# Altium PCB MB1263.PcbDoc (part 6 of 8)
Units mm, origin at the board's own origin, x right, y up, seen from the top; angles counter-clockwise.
Board outline 86 x 120 mm, 6 copper layers (Top Layer, Signal Layer 1, Signal Layer 2, Signal Layer 3, Signal Layer 4, Bottom Layer), stack 1.556 mm thick; 392 components, 421 nets, 1978 pads, 1444 vias.
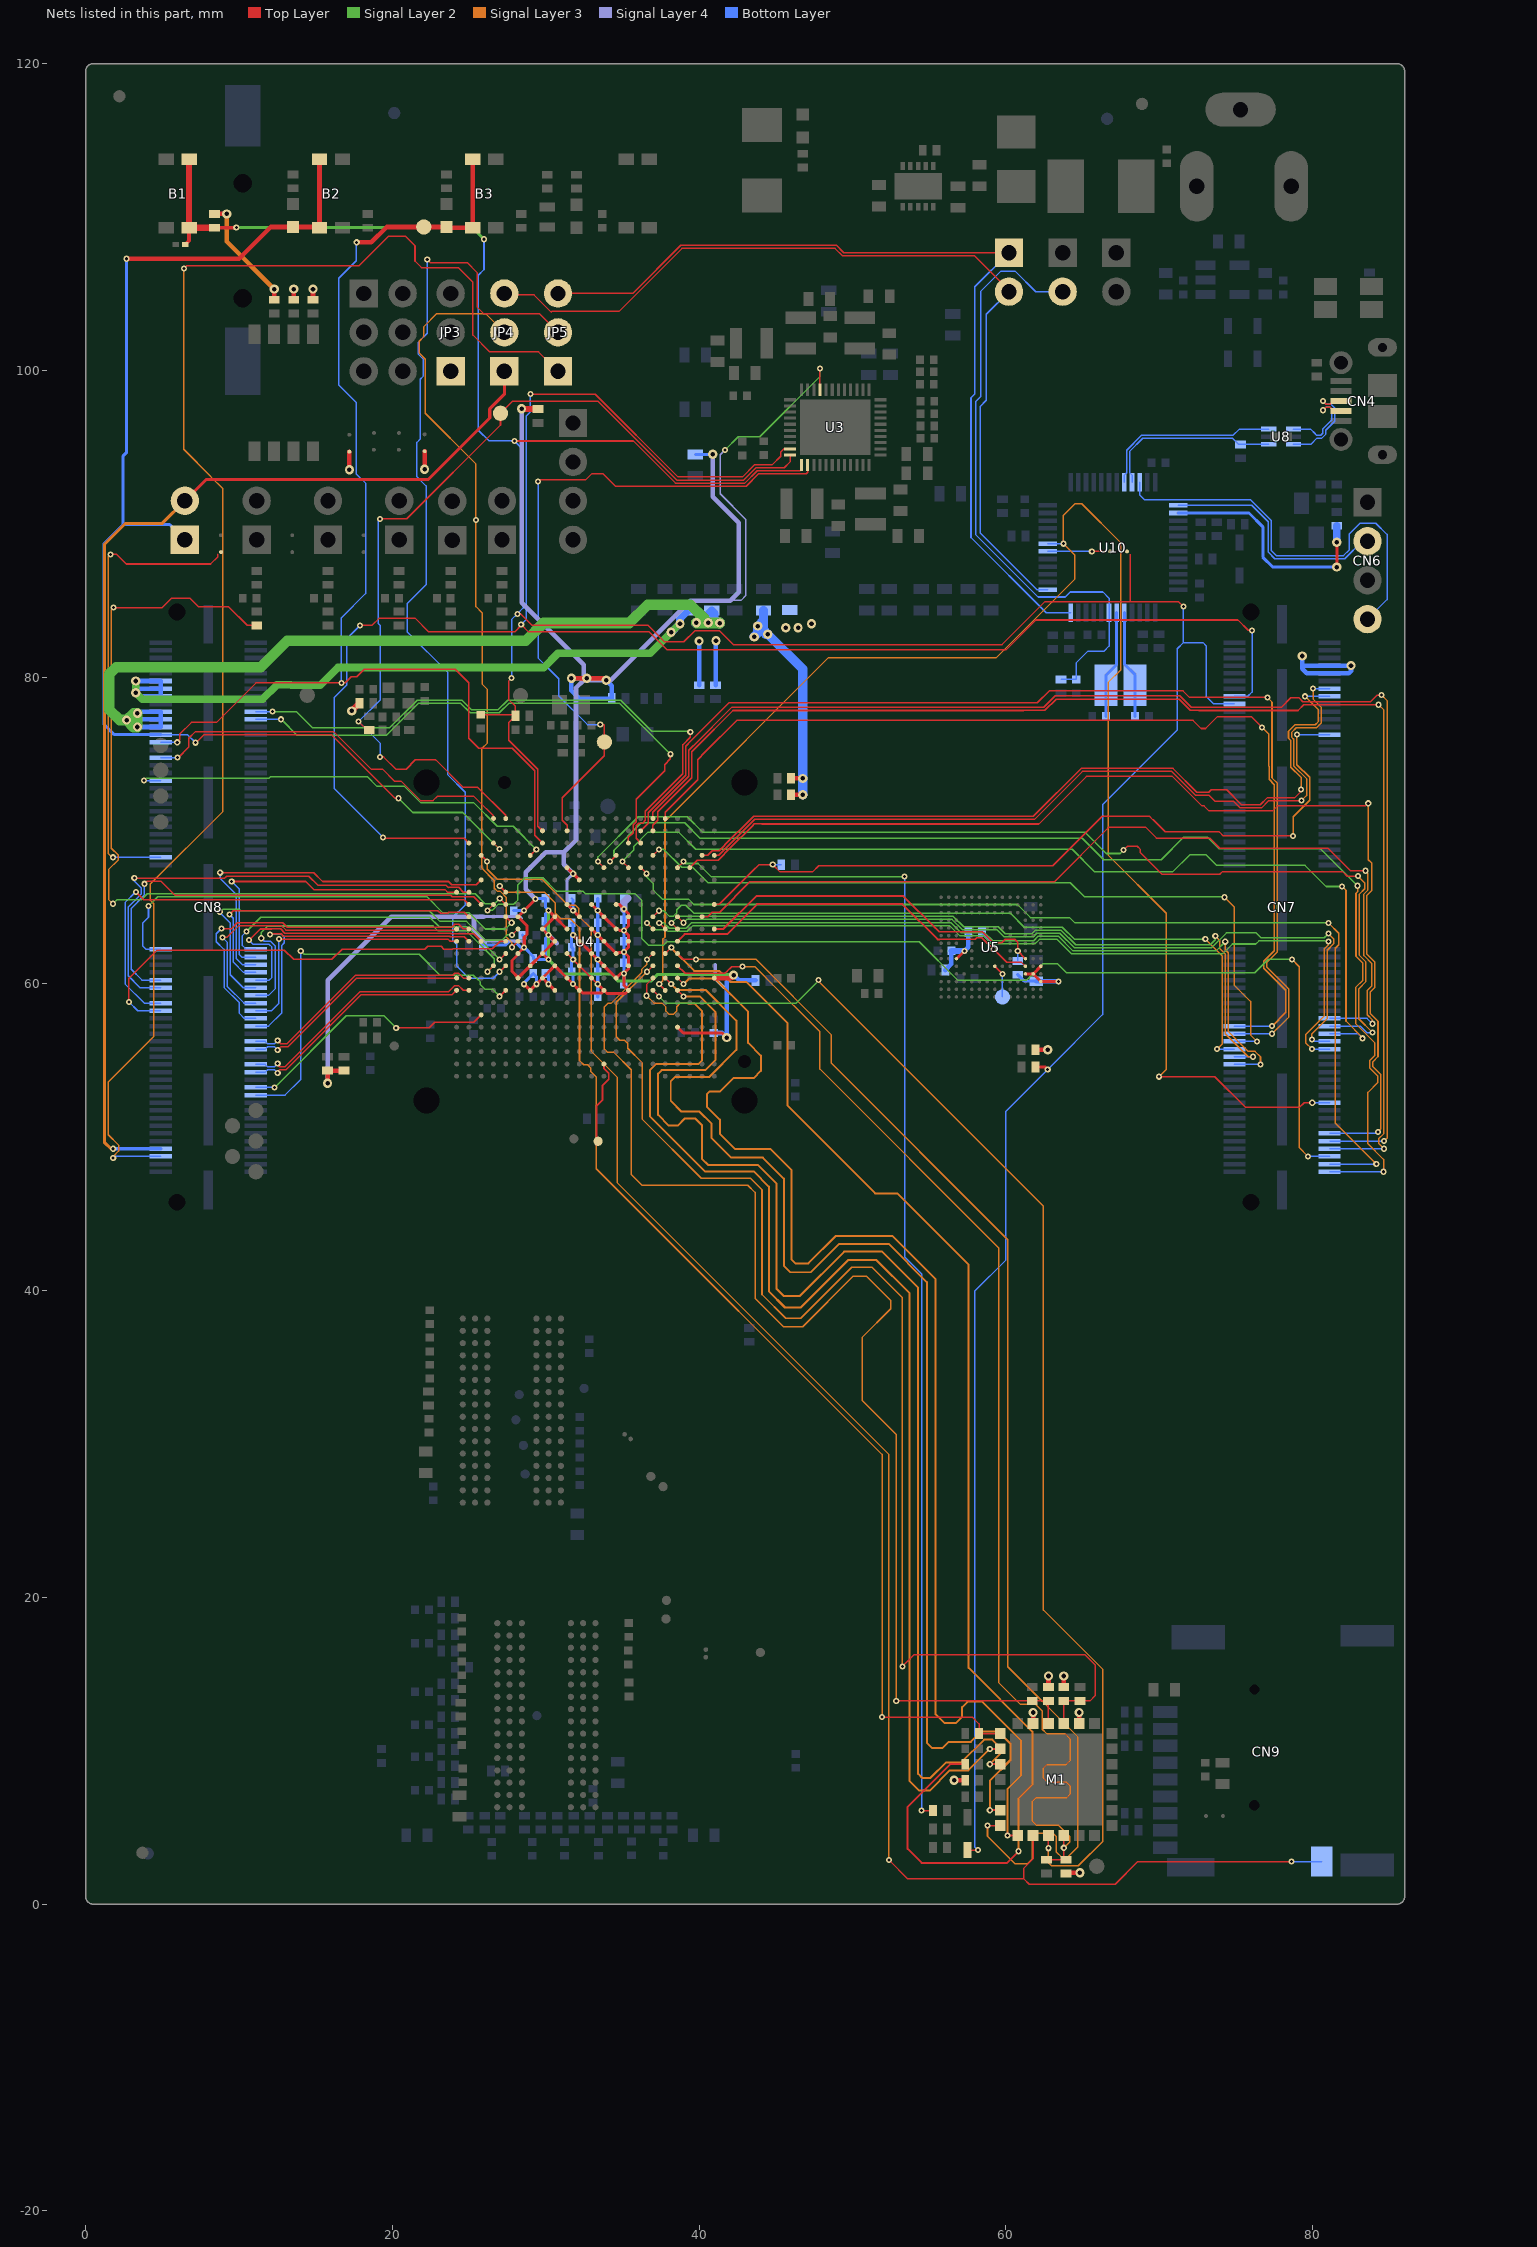
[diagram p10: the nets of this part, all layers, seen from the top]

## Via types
v1: diameter 0.4, hole 0.2, Top Layer to Bottom Layer, tented both sides, 771 vias
v2: diameter 0.6, hole 0.3, Top Layer to Bottom Layer, tented both sides, 670 vias
v3: diameter 0.4, hole 0.2, Top Layer to Bottom Layer, 3 vias

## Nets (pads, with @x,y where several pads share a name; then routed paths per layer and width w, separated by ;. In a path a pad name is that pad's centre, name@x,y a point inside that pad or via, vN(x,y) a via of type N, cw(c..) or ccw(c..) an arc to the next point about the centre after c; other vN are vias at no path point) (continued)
NetTP17_1: TP17.1 U4.K21 | length 5.6
  Top Layer w0.12: TP17.1@33.5,49.75 33.49,49.74 TP17.1@33.41,49.74 33.32,49.83 33.32,52.045 33.66,52.389 33.68,52.409 33.69,52.42 33.69,53.37 34.11,53.79 34.11,54.169 33.79,54.489 U4.K21@33.79,54.78
NetTP31_1: TP31.1 U5.H5 | length 2.2
  Top Layer w0.13: U5.H5@59.275,61.15 v1(59.775,60.65)
  Bottom Layer w0.1: TP31.1@59.775,59.15 v1(59.775,60.65)
NJTRST: CN7.102 U4.E15 U10.19 | length 104.2
  Top Layer w0.1: v1@37.4,59.97 U4.E15@37.79,59.58 ; v1(69.975,53.95) 73.616,53.95 75.616,51.95 79.15,51.95 79.45,52.25 v1(79.975,52.25)
  Signal Layer 3 w0.1: v1@37.4,59.975 37.405,59.98 37.626,60.201 37.626,62.906 37.775,63.055 37.775,70.608 48.442,81.275 59.386,81.275 64.5,86.389 64.5,87.95 v1(63.75,88.7) 63.75,90.55 64.5,91.3 64.95,91.3 67.5,88.75 67.5,80.484 66.66,79.644 66.66,68.399 70.45,64.609 70.45,54.425 v1(69.975,53.95)
  Bottom Layer w0.1: U10.19@62.725,88.7 v1(63.75,88.7) ; v1(79.975,52.25) CN7.102@81.1,52.25
  other v1: 37.4,59.985
NRST: B1.1 B1.2 C34.2 CN7.17 D2.2 R8.1 R27.2 R54.1 SB8.2 U2.1 U3.1 U4.R2 | length 235.1
  Top Layer w0.09: 27.575,76.738 27.575,75.894 29.485,73.984 29.485,70.285 U4.R2@29.79,69.98 ; D2.2@57.5,3.53 v1(58.17,3.53) ; 68.1,88 68.1,84.925 68.125,84.9
  Top Layer w0.1: C34.2@25.75,77.55 27.95,77.55 R27.2@28.025,77.475 ; 27.575,76.738 27.575,77.025 R27.2@28.025,77.475 ; v1(27.775,79.95) 27.575,79.75 27.575,78.55 28.025,78.1 R27.2@28.025,77.475 ; v1(27.951,95.405) 27.961,95.395 35.714,95.395 38.459,92.65 42.989,92.65 43.795,93.456 46.577,93.456 46.679,93.558 U3.1@46.679,93.836 ; v1(28.15,84.125) 28.35,84.125 29.1,83.375 36.675,83.375 37.75,82.3 39,82.3 39.725,83.025 41.325,83.025 42.225,82.125 59.75,82.125 62.525,84.9 68.125,84.9 71.275,84.9 v1(71.575,84.6)
  Top Layer w0.2: R8.1@8.4,109.3 9.8,109.3 v1(9.825,109.325) ; R54.1@61.925,54.575 62.575,54.575 v1(62.725,54.425)
  Top Layer w0.25: U2.1@6.5,108.2 6.75,108.45 B1.2@6.75,109.3
  Top Layer w0.4: B1.1@6.75,113.75 B1.2@6.75,109.3 R8.1@8.4,109.3
  Signal Layer 2 w0.2: v1(9.825,109.325) 25.2,109.325 v1(25.975,108.55)
  Bottom Layer w0.1: v1(25.975,108.55) 25.975,106.575 25.6,106.2 25.6,96.1 26.295,95.405 v1(27.951,95.405) 28.525,94.831 28.525,84.5 v1(28.15,84.125) 27.775,83.75 v1(27.775,79.95) ; v1(58.17,3.53) 57.975,3.725 57.975,39.975 60,42 60,51.7 v1(62.725,54.425) 66.3,58 66.3,71.675 71.175,76.55 71.175,81.85 71.575,82.25 ; v1(71.575,84.6) 71.575,82.25 ; CN7.17@74.9,78.25 73.55,78.25 73.05,78.75 73.05,82.05 72.85,82.25 71.575,82.25
OSC_IN: C73.1 U10.5 X3.2 | length 7
  Bottom Layer w0.2: U10.5@67.725,84.2 67.725,80.85 68.425,80.15 X3.2@68.425,79.475 C73.1@68.425,77.45
OSC_OUT: C74.1 U10.6 X3.1 | length 7
  Bottom Layer w0.2: C74.1@66.525,77.45 X3.1@66.525,79.475 66.525,80.125 67.225,80.825 U10.6@67.225,84.2
OTG_ID: CN8.98 U4.Y17 | length 17.3
  Top Layer w0.09: v1(20.25,57.125) 22.39,57.125 22.75,57.485 25.295,57.485 U4.Y17@25.79,57.98
  Signal Layer 2 w0.1: v1(12.325,53.25) 17,57.925 19.45,57.925 v1(20.25,57.125)
  Bottom Layer w0.1: CN8.98@11.1,53.25 v1(12.325,53.25)
OTG_VBUS: CN8.100 U4.V15 | length 26.6
  Top Layer w0.1: v1@27,59.19 U4.V15@27.39,59.58
  Signal Layer 2 w0.1: v1(14.025,62.15) 14.25,61.925 21.75,61.925 23.105,60.57 25.27,60.57 25.51,60.33 25.535,60.33 25.74,60.125 25.74,59.95 26.05,59.64 26.544,59.64 v1(26.995,59.19)
  Bottom Layer w0.1: CN8.100@11.1,52.75 13,52.75 14.025,53.775 v1(14.025,62.15)
PA0_WKUP: CN7.15 U3.43 U4.AA3 | length 122.9
  Top Layer w0.09: 19.885,69.485 24.685,69.485 U4.AA3@24.99,69.18
  Top Layer w0.1: v1(17.9,83.375) 18.675,83.375 19.125,83.825 21.5,83.825 22.375,82.95 27.975,82.95 28.4,83.375 v1(28.4,83.425) 28.875,82.95 36.75,82.95 37.925,81.775 60,81.775 61.95,83.725 75.125,83.725 75.8,83.05 v1(76.05,83.05) ; v1(19.4,69.55) 19.465,69.485 19.885,69.485 ; v1(29,98.45) 33.225,98.45 38.625,93.05 42.824,93.05 43.63,93.856 44.781,93.856 45.327,94.402 45.327,94.681 45.532,94.886 U3.43@45.929,94.886
  Bottom Layer w0.1: v1(17.9,83.375) 17.025,82.5 17.025,79.48 16.2,78.655 16.2,72.75 v1(19.4,69.55) ; v1(28.4,83.425) 28.725,83.75 28.725,97.025 29,97.3 v1(29,98.45) ; CN7.15@74.9,78.75 75.775,78.75 76.05,79.025 v1(76.05,83.05)
PA13: B2.1 B2.2 CN8.25 JP6.1 LD2.2 U4.W3 | length 83.5
  Top Layer w0.1: v1(7.175,75.725) 7.2,75.725 7.725,76.25 16.025,76.25 20.171,72.104 v1(20.401,72.104) ; U4.W3@26.59,69.18 v1@26.98,68.79
  Top Layer w0.3: v1(2.675,107.275) 10,107.275 12.075,109.35 LD2.2@13.525,109.35 15.2,109.35 B2.1@15.25,109.3 B2.2@15.25,113.75
  Signal Layer 2 w0.1: v1(20.401,72.104) 20.397,72.1 21.322,71.175 24.589,71.175 v1(26.98,68.785)
  Bottom Layer w0.1: CN8.25@4.9,76.25 6.65,76.25 v1(7.175,75.725)
  Bottom Layer w0.2: v1@2.68,107.27 2.68,94.655 2.45,94.425 2.45,89.95 ; CN8.25@4.9,76.25 1.875,76.25 1.2,76.925 1.2,88.7 2.45,89.95 ; JP6.1@6.475,88.955 5.48,89.95 2.45,89.95
  Bottom Layer w0.3: v1(2.675,107.275) v1@2.68,107.27
PA14: B3.1 B3.2 CN8.27 LD3.2 TP1.1 U4.R3 | length 79.4
  Top Layer w0.09: 14.725,79.625 v1(16.675,79.625) 16.913,79.625 17.328,80.04 17.69,80.04 18.17,80.52 24.109,80.52 24.995,79.634 24.995,76.005 25.63,75.37 27.83,75.37 29.295,73.905 29.295,69.675 U4.R3@29.79,69.18
  Top Layer w0.1: v1(5.975,75.75) 6.125,75.9 6.125,76.275 6.9,77.05 8.533,77.05 11.108,79.625 14.725,79.625
  Top Layer w0.3: v1(17.675,108.35) 18.625,108.35 19.625,109.35 TP1.1@22.05,109.35 LD3.2@23.525,109.35 23.575,109.3 B3.1@25.25,109.3 B3.2@25.25,113.75
  Bottom Layer w0.1: CN8.27@4.9,75.75 v1(5.975,75.75) ; v1(16.675,79.625) 16.675,83.875 18.25,85.45 18.25,92.65 17.65,93.25 17.65,97.9 16.5,99.05 16.5,106 17.65,107.15 17.65,108.325 v1(17.675,108.35)
PF12: R21.1 U4.V8 | length 56.7
  Top Layer w0.1: v1(1.825,84.529) 4.979,84.529 5.6,85.15 6.8,85.15 7.375,84.575 9.334,84.575 10.534,83.375 R21.1@11.15,83.375 ; v1@27,65.57 U4.V8@27.39,65.18
  Signal Layer 2 w0.1: v1(1.775,65.225) 2.028,65.478 3.625,65.478 4.022,65.875 25.399,65.875 26.045,65.23 26.655,65.23 v1(27,65.575)
  Signal Layer 3 w0.1: v1(1.775,65.225) 1.5,65.5 1.5,67.45 2.125,68.075 2.125,68.398 1.675,68.848 1.675,84.379 v1(1.825,84.529)
PF12_MB: CN8.57 SB5.2 | length 30.7
  Top Layer w0.1: v1(1.625,88.004) 1.621,88 1.625,88 2.025,88 2.65,87.375 8.15,87.375 8.625,87.85 8.625,88
  Signal Layer 3 w0.1: v1(1.625,88.004) 1.475,87.854 1.475,68.5 1.722,68.253 v1(1.775,68.253)
  Signal Layer 4 w0.1: v1(1.775,68.253) v1@1.797,68.253
  Bottom Layer w0.1: v1(1.775,68.253) 1.778,68.25 CN8.57@4.9,68.25
PMIC_WAKEUP: TP5.1 U3.2 U4.N2 | length 45.4
  Top Layer w0.09: U4.N2@31.39,69.98 31.39,70.348 31.085,70.653 31.085,72.13 33.825,74.871 TP5.1@33.825,75.775
  Top Layer w0.1: v1(29.5,92.75) 29.605,92.855 32.595,92.855 32.99,93.25 33.75,93.25 34.55,92.45 43.072,92.45 43.878,93.256 46.977,93.256 47.079,93.358 U3.2@47.079,93.836 ; v1(33.552,76.904) 33.796,76.904 33.825,76.875 TP5.1@33.825,75.775
  Bottom Layer w0.1: v1(29.5,92.75) 29.5,81.25 30.85,79.9 30.85,78.775 32.721,76.904 v1(33.552,76.904)
PWR_ON: R302.1 TP2.1 U3.44 U4.V1 | length 61.6
  Top Layer w0.09: 20.679,74.004 20.9,74.004 21.494,74.597 22.841,74.597
  Top Layer w0.1: v1(17.8,77.1) 18.35,76.55 R302.1@18.5,76.55 ; v1(19.2,74.8) 19.424,74.8 20.221,74.004 20.679,74.004 ; v1(19.2,90.3) 19.22,90.32 20.937,90.32 27.05,96.433 TP2.1@27.05,97.2 27.846,97.996 33.396,97.996 38.542,92.85 42.907,92.85 43.713,93.656 45.552,93.656 45.929,94.033 U3.44@45.929,94.486 ; 22.841,74.597 24.613,72.825 25.556,72.825 27.39,70.991 U4.V1@27.39,70.78
  Bottom Layer w0.1: v1(19.2,74.8) 19.2,75.7 v1(17.8,77.1) 19.2,78.5 19.2,83.375 19.075,83.5 19.075,90.175 v1(19.2,90.3)
QSPI_BK1_IO0: CN8.76 U4.AB10 | length 21.4
  Top Layer w0.1: v1(8.925,63.025) 8.925,63.05 9.241,63.05 9.971,63.78 12.785,63.78 13.059,63.505 24.115,63.505 U4.AB10@24.19,63.58
  Bottom Layer w0.1: v1(8.925,63.025) 9.225,62.725 9.225,59.85 10.325,58.75 CN8.76@11.1,58.75
QSPI_BK1_IO1: CN8.78 U4.AB11 | length 17.5
  Top Layer w0.1: v1(12.6,62.925) 23.63,62.925 23.776,62.78 U4.AB11@24.19,62.78
  Bottom Layer w0.1: CN8.78@11.1,58.25 12.125,58.25 12.6,58.725 v1(12.6,62.925)
QSPI_BK1_IO2: CN8.80 U4.AA10 | length 24.1
  Top Layer w0.09: 12.6,63.98 12.605,63.975 12.865,63.975 13.14,63.7 23.879,63.7 24.063,63.885 24.316,63.885 24.621,63.58 U4.AA10@24.99,63.58
  Top Layer w0.1: v1(8.85,63.6) 9.508,63.6 9.888,63.98 12.6,63.98
  Bottom Layer w0.1: v1(8.85,63.6) 8.525,63.275 8.525,62.75 9.025,62.25 9.025,59.767 10.025,58.767 10.025,58.075 10.35,57.75 CN8.80@11.1,57.75
QSPI_BK1_IO3: CN8.82 U4.AA11 | length 21.3
  Top Layer w0.09: v1(12.025,63.225) 12.07,63.27 12.75,63.27 12.9,63.12 23.732,63.12 23.768,63.085 24.685,63.085 U4.AA11@24.99,62.78
  Bottom Layer w0.1: CN8.82@11.1,57.25 11.925,57.25 12.8,58.125 12.8,62.525 12.95,62.675 12.95,63.07 12.745,63.275 12.075,63.275 v1(12.025,63.225)
QSPI_BK1_NCS: CN8.74 U4.W13 | length 23.6
  Top Layer w0.1: v1@26.2,60.79 U4.W13@26.59,61.18
  Signal Layer 2 w0.1: v1(11.45,62.975) 11.45,63.35 11.875,63.775 22.65,63.775 22.975,63.45 24.829,63.45 26.645,61.635 26.645,61.24 v1(26.195,60.79)
  Bottom Layer w0.1: CN8.74@11.1,59.25 11.925,59.25 12.35,59.675 12.35,62.483 12.058,62.775 11.65,62.775 v1(11.45,62.975)
QSPI_BK2_IO0: CN8.64 U4.AB7 | length 21.1
  Top Layer w0.1: v1(9.525,66.675) 14.35,66.675 14.875,66.15 23.43,66.15 23.6,65.98 U4.AB7@24.19,65.98
  Bottom Layer w0.1: v1(9.525,66.675) 10.025,66.175 10.025,61.9 10.175,61.75 CN8.64@11.1,61.75
QSPI_BK2_IO1: CN8.66 U4.Y6 | length 24.9
  Top Layer w0.09: 23.681,66.675 23.878,66.478 ; 23.881,66.475 25.485,66.475 U4.Y6@25.79,66.78
  Top Layer w0.1: v1(8.775,67.25) 14.875,67.25 15.45,66.675 23.681,66.675
  Bottom Layer w0.1: v1(8.775,67.25) 8.775,66.875 9.825,65.825 9.825,61.65 10.225,61.25 CN8.66@11.1,61.25
QSPI_BK2_IO2: CN8.68 U4.AA9 | length 20.9
  Top Layer w0.09: v1(9.375,64.528) 9.627,64.78 22.959,64.78 23.146,64.593 23.598,64.593 23.689,64.685 24.685,64.685 U4.AA9@24.99,64.38
  Bottom Layer w0.1: v1(9.375,64.528) 9.625,64.279 9.625,61.425 10.3,60.75 CN8.68@11.1,60.75
QSPI_BK2_IO3: CN8.70 U4.Y11 | length 20.6
  Top Layer w0.09: 12.125,63.58 12.709,63.58 12.979,63.31 23.811,63.31 23.846,63.275 25.295,63.275 U4.Y11@25.79,62.78
  Top Layer w0.1: v1(10.65,62.85) 11.38,63.58 12.125,63.58
  Bottom Layer w0.1: v1(10.65,62.85) 10.925,62.575 11.975,62.575 12.15,62.4 12.15,60.425 11.975,60.25 CN8.70@11.1,60.25
QSPI_BK2_NCS: CN8.72 U4.U10 | length 27.1
  Top Layer w0.1: v1@27.8,63.19 U4.U10@28.19,63.58
  Signal Layer 2 w0.1: v1(8.75,64.7) 8.775,64.7 8.953,64.878 10.006,64.878 10.109,64.775 22.4,64.775 23.1,64.075 24.834,64.075 26.069,62.84 27.139,62.84 27.489,63.19 v1(27.795,63.19)
  Bottom Layer w0.1: v1(8.75,64.7) 8.75,64.653 9.425,63.978 9.425,60.6 10.275,59.75 CN8.72@11.1,59.75
QSPI_CLK: CN8.62 U4.V12 | length 20.6
  Top Layer w0.1: v1@27,61.59 U4.V12@27.39,61.98
  Signal Layer 2 w0.1: v1(10.5,63.425) 11.425,64.35 22.426,64.35 23.051,63.725 24.86,63.725 v1(26.995,61.59)
  Bottom Layer w0.1: v1(10.5,63.425) 10.225,63.15 10.225,62.5 10.475,62.25 CN8.62@11.1,62.25
SAI2_FSA: CN7.112 U4.F1 | length 85.8
  Top Layer w0.09: U4.F1@36.99,70.78 36.99,71.198 39.325,73.533 39.325,75.233 39.61,75.518 ; 60.725,78.025 62.458,78.025 63.208,78.775 71.35,78.775 72.1,78.025 73.375,78.025
  Top Layer w0.1: 39.61,75.518 42.117,78.025 60.725,78.025 ; 73.375,78.025 77.95,78.025 78.575,78.65 79.105,78.65 79.355,78.4 83.775,78.4 84.2,78.825 v1(84.5,78.825)
  Signal Layer 3 w0.1: v1(84.5,78.825) 84.85,78.475 84.85,49.95 v1(84.65,49.75)
  Bottom Layer w0.09: CN7.112@81.1,49.75 v1(84.65,49.75)
SAI2_FSB: CN7.14 U4.A4 | length 52.5
  Top Layer w0.09: U4.A4@40.99,68.3 U4.A4@40.99,68.38 41.276,68.38 41.872,68.976 41.872,68.983 43.369,70.48 43.376,70.48 43.621,70.725 43.925,70.725
  Top Layer w0.1: 43.925,70.725 61.866,70.725 64.991,73.85 70.812,73.85 72.362,72.3 73.25,72.3 73.65,71.9 74.859,71.9 75.284,71.475 76.666,71.475 77.141,71.95 v1(79.275,71.95)
  Signal Layer 3 w0.1: v1(79.275,71.95) 79.6,72.275 79.6,73.386 78.775,74.211 78.775,75.955 78.625,76.105 78.625,76.395 78.93,76.7 80.253,76.7 80.575,77.022 80.575,78.025 80.025,78.575 v1(80.025,79.25)
  Bottom Layer w0.1: v1(80.025,79.25) CN7.14@81.1,79.25
SAI2_MCLKA: CN7.110 U4.C5 | length 73.7
  Top Layer w0.09: U4.C5@39.39,67.58 39.885,68.075 41.239,68.075 42.062,68.897 42.062,68.904 43.448,70.29 43.455,70.29 43.59,70.425 44.075,70.425
  Top Layer w0.1: 44.075,70.425 62.15,70.425 65.25,73.525 70.854,73.525 72.779,71.6 72.92,71.6 73.245,71.275 77.375,71.275 77.7,71.6 83.425,71.6 83.612,71.787 83.625,71.8 v1(83.625,71.775)
  Signal Layer 3 w0.1: v1(83.625,71.775) 83.625,68.1 83.85,67.875 83.85,66.084 83.539,65.773 83.539,61.932 84.06,61.411 84.06,59.785 83.754,59.479 83.754,58.071 84.26,57.565 84.26,55.26 83.929,54.929 83.929,54.596 84.45,54.075 84.45,50.55 v1(84.25,50.35)
  Bottom Layer w0.1: CN7.110@81.1,50.25 84.075,50.25 84.175,50.35 v1(84.25,50.35)
SAI2_MCLKB: CN7.16 U4.B4 | length 53
  Top Layer w0.09: U4.B4@40.19,68.38 40.558,68.38 40.863,68.685 41.312,68.685 41.682,69.054 41.682,69.061 43.29,70.67 43.297,70.67 43.552,70.925 43.8,70.925
  Top Layer w0.1: 43.8,70.925 61.783,70.925 64.908,74.05 70.895,74.05 72.445,72.5 73.233,72.5 73.383,72.65 74.392,72.65 75.367,71.675 76.583,71.675 77.058,72.15 78.845,72.15 79.3,72.605 79.3,72.675 v1(79.25,72.675)
  Signal Layer 3 w0.1: v1(79.25,72.675) 79.25,73.453 78.575,74.128 78.575,75.872 78.425,76.022 78.425,76.478 78.847,76.9 80.17,76.9 80.375,77.105 80.375,77.875 v1(79.5,78.75)
  Bottom Layer w0.1: v1(79.5,78.75) CN7.16@81.1,78.75
SAI2_SCKA: CN7.114 U4.F2 | length 85.8
  Top Layer w0.09: U4.F2@36.99,69.98 36.99,70.348 37.295,70.653 37.295,71.234 39.515,73.455 39.515,75.14 39.81,75.435 ; 61.15,77.825 62.527,77.825 63.272,78.57 71.286,78.57 72.021,77.835 72.565,77.835 72.575,77.825
  Top Layer w0.1: 39.81,75.435 42.2,77.825 61.15,77.825 ; 72.575,77.825 79.045,77.825 79.42,78.2 v1(84.3,78.2)
  Signal Layer 3 w0.1: v1(84.3,78.2) 84.65,77.85 84.65,50.25 84.3,49.9 84.3,49.605 84.65,49.255 v1(84.65,49.25)
  Bottom Layer w0.1: CN7.114@81.1,49.25 v1(84.65,49.25)
SAI2_SDA: CN7.118 U4.G5 | length 67
  Top Layer w0.1: U4.G5@36.19,67.58 v1@36.58,67.19
  Signal Layer 2 w0.1: v1(36.58,67.185) 36.58,66.97 37,66.55 37,66.13 37.6,65.53 39.301,65.53 39.656,65.175 60.75,65.175 61.6,64.325 64.15,64.325 64.5,63.975 v1(81.025,63.975)
  Signal Layer 3 w0.1: v1(81.025,63.975) 81.7,63.3 81.7,62.55 81.475,62.325 81.475,50.925 v1(84.15,48.25)
  Bottom Layer w0.1: CN7.118@81.1,48.25 v1(84.15,48.25)
SAI2_SDB: CN7.116 U4.W8 | length 74.6
  Top Layer w0.1: v1@26.2,64.79 U4.W8@26.59,65.18
  Signal Layer 2 w0.1: v1(26.195,64.79) 26.515,64.79 26.925,65.2 27.925,65.2 ; 27.925,65.225 27.945,65.225 28.185,65.465 ; 28.175,65.475 28.175,66.45 28.65,66.925 29.8,66.925 30.7,66.025 30.725,66.025 ; 30.725,66.03 32.445,66.03 32.6,65.875 35.825,65.875 36.25,65.45 36.25,62.975 36.625,62.6 36.712,62.513 ; 36.725,62.525 37.675,62.525 37.9,62.75 54.35,62.75 56.875,60.225 61.325,60.225 62.4,61.3 63.375,61.3 63.95,60.725 76.225,60.725 77.1,61.6 v1(78.65,61.6)
  Signal Layer 3 w0.1: v1(78.65,61.6) 79.125,61.125 79.125,49.325 v1(79.7,48.75)
  Bottom Layer w0.1: v1(79.7,48.75) CN7.116@81.1,48.75
SDMMC1_CDIR: M1.24 R37.2 R38.1 U4.F12 | length 83.1
  Top Layer w0.1: v1@36.6,61.59 U4.F12@36.99,61.98 ; v1(52.85,13.25) R37.2@61.725,13.25 R38.1@62.775,13.25 M1.24@62.775,11.775
  Signal Layer 3 w0.1: v1(36.595,61.59) 36.595,61.285 36.245,60.935 36.245,60.723 34.252,58.73 34.045,58.73 33.825,58.51 33.825,55.75 34.045,55.53 34.445,55.53 35.575,54.4 35.575,47.575 36.275,46.875 43.175,46.875 43.65,46.4 43.65,39.5 45.5,37.65 46.75,37.65 50.05,40.95 50.9,40.95 52.5,39.35 52.5,38.825 50.625,36.95 50.625,32.85 52.85,30.625 v1(52.85,13.25)
SDMMC1_CK: R42.1 U4.E12 | length 87.6
  Top Layer w0.1: U4.E12@37.79,61.98 v1@38.179,62.37
  Top Layer w0.13: R42.1@57.35,9.125 56.375,9.125 53.6,6.35 53.6,3.6 54.5,2.7 60.075,2.7 v1(60.825,3.45)
  Signal Layer 3 w0.13: v1(38.185,62.37) 38.185,62.34 39.675,60.85 41.317,60.85 42.057,60.11 43.1,60.11 45.75,57.46 45.75,52.075 51.475,46.35 52.925,46.35 57.575,41.7 57.575,15.4 61.725,11.25 61.725,7.8 60.825,6.9 v1(60.825,3.45)
SDMMC1_CKIN: M1.10 U4.F15 | length 81.9
  Top Layer w0.1: U4.F15@36.99,59.58 v1@37.38,59.19 ; v1(62.775,3.65) M1.10@62.775,4.475
  Signal Layer 2 w0.1: v1@37.38,59.185 37.387,59.177 37.814,58.75 46.325,58.75 47.8,60.225 47.825,60.25 47.8,60.275 47.775,60.3 v3(47.775,60.25)
  Signal Layer 3 w0.1: v1@37.375,59.139 37.393,59.157 37.4,59.164 37.387,59.177 v1@37.38,59.185 ; v3(47.775,60.25) 47.75,60.25 47.762,60.237 47.825,60.175 47.8,60.15 62.45,45.5 62.45,19.175 66.325,15.3 66.325,4.1 64.725,2.5 62.975,2.5 62.775,2.7 v1(62.775,3.65)
  other v1: 37.38,59.17
SDMMC1_CMD: M1.7 U4.D12 | length 83.1
  Top Layer w0.1: U4.D12@38.59,61.98 38.97,61.6 v1(39.8,61.6) ; v1(58.8,5.125) M1.7@59.625,5.125
  Signal Layer 3 w0.1: v1(39.8,61.6) 43.7,61.6 48.625,56.675 48.625,54.825 60.125,43.325 60.125,15.475 64.7,10.9 64.7,3.75 64,3.05 63.65,3.05 63.275,3.425 63.275,4.425 63.075,4.625 62.1,4.625 61.725,4.25 61.725,2.95 61.425,2.65 60.575,2.65 58.8,4.425 v1(58.8,5.125)
SDMMC1_D0: M1.6 U4.E14 | length 83.1
  Top Layer w0.1: U4.E14@37.79,60.38 v1@38.179,59.99
  Top Layer w0.13: v1(58.95,6.125) M1.6@59.625,6.125
  Signal Layer 3 w0.1: v1(38.179,59.985) v1@38.285,59.985
  Signal Layer 3 w0.13: v1(38.179,59.985) 38.564,59.6 40.425,59.6 42.425,57.6 42.425,55.705 40.645,53.925 38.425,53.925 38.15,53.65 38.15,52.375 38.85,51.675 40.025,51.675 40.8,50.9 40.8,49.975 42.1,48.675 44.15,48.675 45.525,47.3 45.525,41.625 45.95,41.2 47.275,41.2 49.125,43.05 52.35,43.05 54.85,40.55 54.85,10.525 55.2,10.175 55.85,10.175 56.264,10.589 57.714,10.589 58.375,11.25 59.5,11.25 60.3,10.45 60.3,9.4 58.95,8.05 v1(58.95,6.125)
SDMMC1_D0DIR: M1.23 R39.1 R40.2 U4.F13 | length 83.3
  Top Layer w0.1: v1@36.6,60.79 U4.F13@36.99,61.18 ; v1(53.25,15.5) 54,16.25 65.175,16.25 65.825,15.6 65.825,13.6 65.475,13.25 R40.2@64.825,13.25 R39.1@63.775,13.25 M1.23@63.775,11.775
  Signal Layer 3 w0.1: v1(36.595,60.79) 34.6,58.795 34.6,56.55 34.82,56.33 35.135,56.33 35.34,56.125 35.34,55.81 36.3,54.85 36.3,51.166 40.141,47.325 43.35,47.325 44.1,46.575 44.1,39.75 45.65,38.2 46.625,38.2 49.95,41.525 51.275,41.525 53.25,39.55 v1(53.25,15.5)
SDMMC1_D1: M1.8 U4.D14 | length 83.4
  Top Layer w0.1: U4.D14@38.59,60.38 v1@38.98,59.99
  Top Layer w0.13: v1(60.1,4.475) M1.8@60.775,4.475
  Signal Layer 3 w0.13: v1(38.98,59.985) 39.345,60.35 41.025,60.35 43.2,58.175 43.2,56.15 44.025,55.325 44.025,54.325 43.55,53.85 42.225,53.85 41.375,53 40.7,53 40.5,52.8 40.5,52 41.35,51.15 41.35,50.225 42.325,49.25 44.625,49.25 46.025,47.85 46.025,42.025 46.275,41.775 47.125,41.775 48.925,43.575 52.6,43.575 55.425,40.75 55.425,12.375 56,11.8 56.725,11.8 57.15,12.225 57.15,12.85 57.5,13.2 58.45,13.2 60.975,10.675 60.975,8.375 60.1,7.5 v1(60.1,4.475)
SDMMC1_D2: M1.2 U4.F14 | length 83.5
  Top Layer w0.1: v1(36.575,59.225) 36.575,59.965 U4.F14@36.99,60.38
  Top Layer w0.13: v1(58.95,10.125) M1.2@59.625,10.125
  Signal Layer 3 w0.1: v1(36.575,59.225) 37.05,58.75 37.575,58.75 37.835,58.49 37.835,58.225 38.04,58.02 38.33,58.02 38.535,58.225 38.535,58.514 38.755,58.735 39.275,58.735
  Signal Layer 3 w0.13: 39.275,58.735 39.675,58.735 40.2,58.21 40.2,55.025 39.95,54.775 37.175,54.775 36.8,54.4 36.8,51.35 40.375,47.775 43.55,47.775 44.55,46.775 44.55,39.95 45.6,38.9 46.625,38.9 49.725,42 51.55,42 53.725,39.825 53.725,8.025 54.35,7.4 55.025,7.4 56.35,8.725 57.55,8.725 v1(58.95,10.125)
SDMMC1_D3: M1.3 U4.D15 | length 83.2
  Top Layer w0.1: U4.D15@38.59,59.58 v1@38.98,59.19
  Top Layer w0.13: v1(58.95,9.125) M1.3@59.625,9.125
  Signal Layer 3 w0.13: v1(38.98,59.185) 40.04,59.185 41.075,58.15 41.075,55.05 40.405,54.38 37.555,54.38 37.325,54.15 37.325,51.455 38.028,50.752 38.603,50.752 39.075,51.225 39.753,51.225 40.178,50.8 40.178,48.602 40.58,48.2 43.825,48.2 45.03,46.995 45.03,40.14 45.52,39.65 46.55,39.65 49.45,42.55 51.925,42.55 54.275,40.2 54.275,8.5 54.55,8.225 55.075,8.225 56.1,9.25 57.1,9.25 58.575,10.725 59.125,10.725 59.7,10.15 59.7,9.875 v1(58.95,9.125)
SDMMC1_D123DIR: M1.11 R48.2 R49.1 U4.D13 | length 82.7
  Top Layer w0.09: U4.D13@38.59,61.18 39.085,60.685 41.685,60.685 41.825,60.825
  Top Layer w0.1: 41.825,60.825 42.125,61.125 v1(42.825,61.125) ; R48.2@62.65,2.9 R49.1@63.925,2.9 63.775,3.05 v1(63.775,3.675) M1.11@63.775,4.475
  Signal Layer 3 w0.1: v1(42.825,61.125) 43.65,61.125 44.4,60.375 44.4,60.35 47.875,56.875 47.875,54.45 59.525,42.8 59.525,14.45 60.95,13.025 61.95,13.025 62.375,12.6 62.375,11.4 62.65,11.125 63.85,11.125 64.2,10.775 64.2,9.375 63.925,9.1 62.675,9.1 62.45,8.875 62.45,8.225 62.725,7.95 63.95,7.95 64.2,7.7 64.2,7.175 63.95,6.925 61.95,6.925 61.725,6.7 61.725,5.425 62,5.15 63.425,5.15 64.175,4.4 64.175,4.075 v1(63.775,3.675)
SDMMC2_CK: R100.1 U4.A10 U5.M6 | length 24
  Top Layer w0.09: 55.361,63.686 55.647,63.4 58.45,63.4 59.175,62.675 59.725,62.675 59.95,62.9 60.575,62.9 60.775,62.7 v1(60.775,62.15) U5.M6@61.275,61.65
  Top Layer w0.13: U4.A10@40.99,63.58 41.587,63.58 43.732,65.725 53.322,65.725 55.361,63.686
  Bottom Layer w0.1: R100.1@60.775,61.5 v1(60.775,62.15)
SDMMC2_CMD: R901.1 U4.D11 U5.M5 | length 26.9
  Top Layer w0.09: 55.668,62.9 58,62.9 58.094,62.994 58.471,62.994 58.471,62.991 v1(59.2,62.262) 60.062,61.4 61.025,61.4
  Top Layer w0.1: 61.03,61.397 61.027,61.4 61.025,61.4 U5.M5@61.275,61.15
  Top Layer w0.13: U4.D11@38.59,62.78 39.06,63.25 41.825,63.25 43.775,65.2 53.25,65.2 55.55,62.9 55.668,62.9
  Bottom Layer w0.09: R901.1@58.45,63.4 58.45,63.275 59.2,62.525 v1(59.2,62.262)
SDMMC3_CK: CN7.89 U4.D10 | length 47.8
  Top Layer w0.1: v1@38.2,63.97 U4.D10@38.59,63.58
  Signal Layer 2 w0.1: v1(38.2,63.975) 38.625,64.4 56.574,64.4 57.249,63.725 59.503,63.725 59.953,63.275 61.709,63.275 61.934,63.5 63.599,63.5 64.549,62.55 73.322,62.55 73.654,62.881 v1(73.654,63.128)
  Signal Layer 3 w0.1: v1(73.654,63.128) 73.95,62.832 73.95,62.3 74.3,61.95 74.3,56.75 75.8,55.25 v1(76.1,55.25)
  Bottom Layer w0.1: CN7.89@74.9,55.25 v1(76.1,55.25)
SDMMC3_CMD: CN7.80 U4.B9 | length 60.4
  Top Layer w0.09: U4.B9@40.19,64.38 40.558,64.38 40.863,64.685 41.343,64.685 43.308,66.65 47.003,66.65
  Top Layer w0.1: 47.003,66.65 63.15,66.65 66.725,70.225 69.1,70.225 69.815,69.51 73.3,69.51 73.3,69.5 73.95,68.85 81,68.85 82.475,67.375 v1(83.45,67.375)
  Signal Layer 3 w0.1: v1(83.45,67.375) 83.6,67.225 83.6,66.116 83.339,65.856 83.339,61.849 83.86,61.329 83.86,59.868 83.554,59.562 83.554,57.988 83.9,57.642 v1(83.9,57.4)
  Bottom Layer w0.1: CN7.80@81.1,57.75 83.55,57.75 v1(83.9,57.4)
SDMMC3_D0: CN7.91 U4.E10 | length 49.9
  Top Layer w0.1: v1@37.4,63.97 U4.E10@37.79,63.58
  Signal Layer 2 w0.1: v1(37.4,63.975) 37.705,63.975 38.055,63.625 39.142,63.625 39.517,64 56.408,64 57.083,63.325 58.63,63.325 59.143,62.812 61.812,62.812 62.1,63.1 63.433,63.1 64.383,62.15 73.7,62.15 v1(74.3,62.75)
  Signal Layer 3 w0.1: v1(74.3,62.75) 74.3,62.233 74.5,62.033 74.5,56.9 75.8,55.6 76.245,55.6 76.6,55.245 v1(76.6,54.75)
  Bottom Layer w0.1: CN7.91@74.9,54.75 v1(76.6,54.75)
SDMMC3_D1: CN7.87 U4.F9 | length 46.5
  Top Layer w0.1: U4.F9@36.99,64.38 v1@37.38,64.77
  Signal Layer 2 w0.1: v1(37.385,64.77) 37.69,64.77 38.04,64.42 38.33,64.42 38.535,64.625 38.535,64.837 38.828,65.13 39.135,65.13 39.665,64.6 60.295,64.6 61.195,63.7 63.681,63.7 64.456,62.925 v1(73,62.925)
  Signal Layer 3 w0.1: v1(73,62.925) 74.1,61.825 74.1,56.075 v1(73.775,55.75)
  Bottom Layer w0.1: v1(73.775,55.75) CN7.87@74.9,55.75
SDMMC3_D2: CN7.86 U4.D9 | length 53.1
  Top Layer w0.1: U4.D9@38.59,64.38 v1@38.98,63.99
  Signal Layer 2 w0.1: v1(38.98,63.985) 39.195,64.2 56.491,64.2 57.166,63.525 59.42,63.525 59.87,63.075 61.792,63.075 62.017,63.3 63.516,63.3 64.466,62.35 73.405,62.35 74.38,63.325 76.32,63.325 76.645,63 80.755,63 80.755,63.004 v1(81.029,63.278)
  Signal Layer 3 w0.1: v1(79.95,56.375) 79.95,56.75 80.95,57.75 80.95,62.2 81.375,62.625 81.375,62.92 81.029,63.266 v1(81.029,63.278)
  Bottom Layer w0.1: v1(79.95,56.375) 80.075,56.25 CN7.86@81.1,56.25
SDMMC3_D3: CN7.88 U4.F10 | length 55.7
  Top Layer w0.1: v1@36.6,63.97 U4.F10@36.99,63.58
  Signal Layer 2 w0.1: v1(36.6,63.975) 37.05,63.525 37.872,63.525 37.972,63.425 39.225,63.425 39.6,63.8 56.325,63.8 57,63.125 58.547,63.125 59.06,62.612 61.895,62.612 62.183,62.9 63.35,62.9 64.3,61.95 74.125,61.95 74.775,62.6 76.295,62.6 76.495,62.8 81.025,62.8 v1(81.025,62.775)
  Signal Layer 3 w0.1: v1(79.95,55.75) 79.55,56.15 79.55,56.7 80.75,57.9 80.75,62.283 81.025,62.558 v1(81.025,62.775)
  Bottom Layer w0.1: v1(79.95,55.75) CN7.88@81.1,55.75
SPDIF_RX: CN7.120 U4.J4 | length 77.7
  Top Layer w0.1: v1@34.2,67.99 U4.J4@34.59,68.38
  Signal Layer 2 w0.1: v1(34.195,67.99) 34.45,68.246 34.45,68.72 36.23,70.5 39.06,70.5 40.06,69.5 64.975,69.5 66.375,68.1 70.125,68.1 71.6,69.575 73.125,69.575 73.875,68.825 80.5,68.825 v1(82.925,66.4)
  Signal Layer 3 w0.1: v1(82.925,66.4) 82.939,66.386 82.939,66.021 82.825,65.907 82.825,61.798 83.275,61.348 83.275,60.233 82.8,59.758 82.8,57.41 84.06,56.15 84.06,55.343 83.729,55.012 83.729,54.513 84.25,53.992 84.25,53.575 83.6,52.925 83.6,49.575 84.625,48.55 v1(84.625,47.75)
  Bottom Layer w0.1: CN7.120@81.1,47.75 v1(84.625,47.75)
SPDIF_TX: CN8.75 U4.AA8 | length 31.2
  Top Layer w0.09: 20.325,65.485 24.685,65.485 U4.AA8@24.99,65.18
  Top Layer w0.1: v1(3.275,66) 3.79,65.485 20.325,65.485
  Bottom Layer w0.1: v1(3.275,66) 2.575,65.3 2.575,60 3.825,58.75 CN8.75@4.9,58.75
SPI1_MISO: CN7.84 U4.H5 | length 63.5
  Top Layer w0.1: v1@35,67.97 U4.H5@35.39,67.58
  Signal Layer 2 w0.1: v1(35,67.975) 35,67.993 35.732,68.725 35.732,68.957 36.674,69.899 38.651,69.899 39.775,68.775 64.325,68.775 65.8,67.3 70.87,67.3 71.995,68.425 73.045,68.425 73.745,67.725 79.5,67.725 80.875,66.35 v1(81.925,66.35)
  Signal Layer 3 w0.1: v1(81.925,66.35) 82.175,66.1 82.175,57.575 83.254,56.496 v1(83.254,56.453)
  Bottom Layer w0.1: CN7.84@81.1,56.75 82.957,56.75 v1(83.254,56.453)
SPI1_MOSI: CN7.82 U4.K5 | length 68
  Top Layer w0.1: v1@33.4,67.97 U4.K5@33.79,67.58 ; v1(67.675,68.725) 67.925,68.975 68.57,68.975 68.775,68.77 68.775,68.551 70.181,67.145 73.95,67.145 74.13,67.325 81.952,67.325 82.252,67.025 v1(82.95,67.025)
  Signal Layer 2 w0.1: v1(33.4,67.975) 33.4,68.275 36.025,70.9 39.226,70.9 40.226,69.9 65.141,69.9 66.541,68.5 67.45,68.5 v1(67.675,68.725)
  Signal Layer 3 w0.1: v1(82.95,67.025) 83.4,66.575 83.4,66.199 83.025,65.824 83.025,61.881 83.475,61.431 83.475,60.15 83,59.675 83,57.725 83.9,56.825 83.901,56.825 v1(83.904,56.828)
  Bottom Layer w0.1: CN7.82@81.1,57.25 83.1,57.25 83.522,56.828 v1(83.904,56.828)
SPI1_NSS: CN7.85 U4.F4 | length 50.5
  Top Layer w0.1: U4.F4@36.99,68.38 v1@37.38,68.77
  Signal Layer 2 w0.1: v1(37.385,68.77) 37.69,68.77 38.86,67.6 39.575,67.6 40.575,66.6 64.2,66.6 65.125,65.675 74.25,65.675 v1(74.25,65.65)
  Signal Layer 3 w0.1: v1(74.25,65.65) 74.875,65.025 74.875,59.934 75.95,58.859 75.95,56.675 v1(76.375,56.25)
  Bottom Layer w0.1: CN7.85@74.9,56.25 v1(76.375,56.25)
SPI1_SCK: CN7.83 U4.G2 | length 72.3
  Top Layer w0.09: U4.G2@36.19,69.98 36.685,70.475 36.685,71.162 39.135,73.612 39.135,74.971 39.13,74.976 39.13,75.505 39.296,75.671
  Top Layer w0.1: 39.296,75.671 41.95,78.325 62.05,78.325 62.825,79.1 71.55,79.1 71.975,78.675 v1(77.05,78.675)
  Signal Layer 3 w0.1: v1(77.05,78.675) 77.35,78.375 77.35,73.425 77.7,73.075 77.7,62.095 77,61.395 77,61.105 78.45,59.655 78.45,57.85 v1(77.35,56.75)
  Bottom Layer w0.1: CN7.83@74.9,56.75 v1(77.35,56.75)
STL_USB_N: U8.6 U10.32 | length 12
  Bottom Layer w0.1: U10.32@67.725,92.7 67.725,93.175 67.875,93.325 67.875,94.794 68.846,95.765 74.815,95.765 75.225,96.175 U8.6@77.14,96.175
STL_USB_P: R51.1 U8.4 U10.33 | length 11.7
  Bottom Layer w0.1: U10.33@68.225,92.7 68.225,93.175 68.065,93.335 68.065,94.715 68.925,95.575 74.775,95.575 75.175,95.175 R51.1@75.3,95.175 U8.4@77.14,95.175
STLCN_USB_N: CN4.2 U8.1 | length 6
  Top Layer w0.1: v1(80.675,97.4) 80.88,97.605 81.12,97.605 81.375,97.35 CN4.2@81.85,97.35
  Bottom Layer w0.1: U8.1@78.75,96.175 79.856,96.175 80.17,95.861 80.17,95.855 80.25,95.775 80.528,95.775 80.656,95.904 80.656,95.907 80.66,95.911 80.66,96.179 81.25,96.769 81.25,97.475 81.12,97.605 80.88,97.605 v1(80.675,97.4)
STLCN_USB_P: CN4.3 U8.3 | length 6.9
  Top Layer w0.1: v1(80.675,98) 80.88,97.795 81.145,97.795 81.3,97.95 81.85,97.95 CN4.3@82.1,97.95
  Bottom Layer w0.1: U8.3@78.75,95.175 79.875,95.175 80.285,95.585 80.606,95.585 80.846,95.825 80.846,95.829 80.85,95.829 80.85,96.1 81.44,96.69 81.44,97.554 81.199,97.795 80.88,97.795 v1(80.675,98)
STLINK_RX: CN2.2 JP4.3 U10.13 | length 58.8
  Top Layer w0.1: JP4.3@27.3,105.015 27.399,104.916 29.234,104.916 30.35,103.8 30.39,103.84 34.773,103.84 38.883,107.95 48.867,107.95 49.347,107.47 57.955,107.47 60.2,105.225 CN2.2@60.2,105.13
  Bottom Layer w0.1: CN2.2@60.2,105.13 58.725,103.655 58.725,98.05 58.325,97.65 58.325,89.4 62.025,85.7 U10.13@62.725,85.7
STLINK_TX: CN2.1 JP5.3 U10.12 | length 59
  Top Layer w0.1: JP5.3@30.8,105.015 35.665,105.015 38.8,108.15 48.95,108.15 49.43,107.67 CN2.1@60.2,107.67
  Bottom Layer w0.1: CN2.1@60.2,107.67 57.975,105.445 57.975,98.459 57.725,98.209 57.725,89.1 62.625,84.2 U10.12@64.225,84.2
STM_JTCK_SWCLK: CN6.2 U10.37 | length 15.4
  Bottom Layer w0.1: U10.37@71.225,91.2 76.025,91.2 77.1,90.125 77.1,88.15 77.525,87.725 82.1,87.725 83.25,88.875 83.56,88.875 CN6.2@83.575,88.86
STM_JTMS_SWDIO: CN6.4 U10.34 | length 27.6
  Bottom Layer w0.1: U10.34@68.725,92.7 68.725,91.875 69.05,91.55 75.958,91.55 77.3,90.208 77.3,88.25 77.625,87.925 82.017,87.925 82.4,88.308 82.4,89.347 83.088,90.035 84.115,90.035 84.85,89.3 84.85,85.055 CN6.4@83.575,83.78
STM_RST: C72.1 JP1.2 R92.1 U10.7 | length 40.9
  Bottom Layer w0.1: R92.1@63.6,79.85 C72.1@64.575,79.85 64.575,80.925 65.325,81.675 66.375,81.675 66.725,82.025 U10.7@66.725,84.2 66.725,85.15 66.325,85.55 64.2,85.55 63.875,85.225 62.1,85.225 58.025,89.3 58.025,97.95 58.35,98.275 58.35,105.15 59.65,106.45 60.625,106.45 61.945,105.13 JP1.2@63.7,105.13
SUB_NRST: CN7.26 R97.1 U4.A8 | length 51.1
  Top Layer w0.09: U4.A8@40.99,65.18 41.3,65.18 43.495,67.375 ; 69.6,70.69 70.385,69.905 73.92,69.905 73.922,69.903
  Top Layer w0.1: 43.499,67.371 43.902,67.775 v1(44.8,67.775) 45.275,67.3 47.4,67.3 47.8,67.7 63.05,67.7 66.275,70.925 69.358,70.925 69.596,70.687 ; 73.92,69.9 74.17,69.65 v1(78.725,69.65)
  Signal Layer 3 w0.09: v1(78.725,69.65) 78.725,70.912 79.795,71.982 79.795,73.466 78.975,74.286 v1(78.975,76.25)
  Bottom Layer w0.1: v1(44.8,67.775) R97.1@45.35,67.775 ; v1(78.975,76.25) CN7.26@81.1,76.25
T_NRST: SB8.1 U10.18 | length 3.7
  Top Layer w0.1: v1(65.6,88.2) 66.45,88.2
  Bottom Layer w0.1: U10.18@62.725,88.2 v1(65.6,88.2)
TIM2_CH4: CN8.37 U4.T4 | length 29.3
  Top Layer w0.1: U4.T4@28.99,68.38 v1@29.38,68.77
  Signal Layer 2 w0.1: v1(3.8,73.25) 3.95,73.4 11.95,73.4 12.05,73.5 18.375,73.5 19,72.875 20.791,72.875 21.841,71.825 25.295,71.825 26.845,70.275 27.88,70.275 v1(29.385,68.77)
  Bottom Layer w0.1: v1(3.8,73.25) CN8.37@4.9,73.25
TIM8_CH4: CN7.81 U4.E1 | length 66.9
  Top Layer w0.09: U4.E1@37.79,70.78 37.79,71.192 39.895,73.297 39.895,74.62 40.405,75.13
  Top Layer w0.1: 40.405,75.13 42.45,77.175 72.2,77.175 72.725,76.65 73.02,76.65 73.795,77.425 76,77.425 v1(76.7,76.725)
  Signal Layer 3 w0.09: 77.155,74.2 77.155,73.344 77.505,72.994 77.505,62.176 76.805,61.476 76.805,61.024 78.25,59.579 78.25,58.15 v1(77.35,57.25)
  Signal Layer 3 w0.1: v1(76.7,76.725) 77.15,76.275 77.15,74.2
  Bottom Layer w0.1: CN7.81@74.9,57.25 v1(77.35,57.25)
TIM12_CH1: CN8.77 U4.V11 | length 30.1
  Top Layer w0.09: 12.778,62.2 12.954,62.2 13.554,61.6 16.058,61.6 16.728,62.27 22.125,62.27 22.305,62.45 23.18,62.45 23.355,62.275 23.95,62.275 ; 23.95,62.285 26.526,62.285 27.021,62.78 U4.V11@27.39,62.78
  Top Layer w0.1: v1(2.825,58.825) 2.825,60.375 4.65,62.2 12.778,62.2
  Bottom Layer w0.1: v1(2.825,58.825) 3.4,58.25 CN8.77@4.9,58.25
UART4_RX: JP5.2 U4.V13 | length 65
  Top Layer w0.1: v1(22.275,107.225) 22.475,107.025 24.875,107.025 25.525,106.375 25.525,104.125 25.95,103.7 29.575,103.7 JP5.2@30.8,102.475 ; v1@27,60.79 U4.V13@27.39,61.18
  Bottom Layer w0.1: v1(22.275,107.225) 22.275,102.418 21.7,101.843 21.7,101.04 22,100.74 22,99.603 21.825,99.428 21.825,95.525 21.6,95.3 21.6,93.065 22.2,92.465 22.2,86.017 20.975,84.792 20.975,82.95 23.625,80.3 23.625,73.625 24.75,72.5 24.75,65.15 23.938,64.338 23.938,62.837 24.2,62.575 24.2,61.175 25,60.375 26.579,60.375 v1(26.995,60.79)
UART4_RX_MB: CN8.115 JP5.1 | length 97.4
  Top Layer w0.1: v1(6.425,106.65) 6.6,106.825 17.825,106.825 19.75,108.75 20.85,108.75 21.475,108.125 21.475,107.125 21.9,106.7 24.3,106.7 25.25,105.75 25.25,102.3 26.35,101.2 29.535,101.2 JP5.1@30.8,99.935
  Signal Layer 3 w0.1: v1(1.8,48.65) 1.8,48.755 2.15,49.105 2.15,49.495 1.475,50.17 1.475,53.6 4.45,56.575 4.45,65.22 4.2,65.47 4.2,66.495 8.95,71.245 8.95,92.275 8.15,93.075 ; v1(6.425,106.65) 6.4,106.625 6.4,94.85 8.162,93.088
  Bottom Layer w0.1: v1(1.8,48.65) 1.9,48.75 CN8.115@4.9,48.75
UART4_TX: JP4.2 U4.U11 | length 50.2
  Top Layer w0.1: v1@27.8,62.39 U4.U11@28.19,62.78
  Signal Layer 3 w0.1: JP4.2@27.3,102.475 26.075,103.7 22.9,103.7 22.057,102.857 22.057,102.2 21.75,101.893 21.75,101.131 22.15,100.731 22.15,97.2 25.45,93.9 v1(25.45,90.25) 25.45,84.6 25.85,84.2 25.85,79.55 26.2,79.2 26.2,75.714 25.83,75.343 25.83,67.547 26.65,66.727 26.65,66.23 26.855,66.025 27.045,66.025 27.43,65.64 27.43,63.06 27.795,62.695 v1(27.795,62.39)
UART4_TX_MB: CN8.113 JP4.1 JP6.2 | length 74.8
  Top Layer w0.2: JP6.2@6.475,91.495 7.855,92.875 22.325,92.875 26.35,96.9 26.35,97.49 27.3,98.44 JP4.1@27.3,99.935
  Signal Layer 3 w0.2: v1(1.8,49.25) 1.65,49.25 1.225,49.675 1.225,88.65 2.6,90.025 5.005,90.025 JP6.2@6.475,91.495
  Bottom Layer w0.2: v1(1.8,49.25) CN8.113@4.9,49.25
USART1_CK: CN8.20 U4.G3 | length 39.9
  Top Layer w0.09: U4.G3@36.19,69.18 35.885,69.485 35.885,70.306 36.053,70.475 36.316,70.475 36.495,70.653 36.495,71.24 38.945,73.691 38.945,74.275
  Top Layer w0.1: 38.94,74.275 38.94,74.891 38.935,74.896 38.935,75.586 38.94,75.591 38.94,75.598 39.425,76.083 v1(39.425,76.425)
  Signal Layer 2 w0.1: v1(12.175,77.75) 13.75,77.75 14.8,76.7 19.817,76.7 21.617,78.5 24.533,78.5 25.158,77.875 26.892,77.875 27.517,78.5 34.883,78.5 36.908,76.475 39.375,76.475 v1(39.425,76.425)
  Bottom Layer w0.1: CN8.20@11.1,77.75 v1(12.175,77.75)
USART1_TX: CN8.22 U4.H3 | length 37.2
  Top Layer w0.09: U4.H3@35.39,69.18 35.39,69.548 35.695,69.853 35.695,70.385 35.885,70.575 35.885,72.023 37.75,73.888 37.75,74.3 38.125,74.675 v1(38.125,74.975)
  Signal Layer 2 w0.1: v1(12.75,77.25) 13.8,76.2 19.6,76.2 21.7,78.3 24.45,78.3 25.075,77.675 26.975,77.675 27.6,78.3 34.8,78.3 v1(38.125,74.975)
  Bottom Layer w0.1: CN8.22@11.1,77.25 v1(12.75,77.25)
USART3_CTS: CN8.31 U4.W1 | length 25.4
  Top Layer w0.1: v1(6,74.75) 6.036,74.75 6.725,75.439 6.725,76.017 7.158,76.45 16.167,76.45 18.609,74.009 19.351,74.009 20.159,73.2 20.589,73.2 21.834,71.955 22.655,71.955 22.925,72.225 25.32,72.225 25.59,71.955 26.59,70.956 U4.W1@26.59,70.78
  Bottom Layer w0.1: CN8.31@4.9,74.75 v1(6,74.75)
USART3_RTS: CN8.69 U4.Y8 | length 30.8
  Top Layer w0.09: 23.8,65.775 23.9,65.675 25.295,65.675 U4.Y8@25.79,65.18
  Top Layer w0.1: v1(3.85,66.525) 4.025,66.7 4.9,66.7 5.82,65.78 23.795,65.78 23.8,65.775
  Bottom Layer w0.1: v1(3.85,66.525) 3.825,66.5 3.825,65.772 2.975,64.922 2.975,60.95 3.675,60.25 CN8.69@4.9,60.25
USART3_RX: CN8.71 U4.AA7 | length 31.7
  Top Layer w0.09: 23.64,66.285 24.316,66.285 24.621,65.98 U4.AA7@24.99,65.98
  Top Layer w0.1: v1(3.175,66.9) 9.075,66.9 9.2,67.025 14.55,67.025 15.15,66.425 23.5,66.425 23.64,66.285
  Bottom Layer w0.1: v1(3.175,66.9) 3.175,66.705 3.525,66.355 3.525,66.345 3.625,66.245 3.625,65.855 2.775,65.005 2.775,60.525 3.55,59.75 CN8.71@4.9,59.75
USART3_TX: CN8.61 U4.V9 | length 29.5
  Top Layer w0.1: U4.V9@27.39,64.38 v1@27.779,63.99
  Signal Layer 2 w0.1: v1(4.1,65.075) 4.7,65.675 22.258,65.675 23.308,64.625 25.008,64.625 26.053,63.58 27.375,63.58 v1(27.779,63.985)
  Bottom Layer w0.1: v1(4.1,65.075) 4.1,64.35 3.725,63.975 3.725,62.475 3.95,62.25 CN8.61@4.9,62.25
USB1_N: CN8.94 U4.AB15 | length 15.5
  Top Layer w0.1: v1(12.525,54.2) 12.525,54.285 12.65,54.41 13.079,54.41 17.969,59.3 23.91,59.3 U4.AB15@24.19,59.58
  Bottom Layer w0.1: CN8.94@11.1,54.25 11.725,54.25 11.88,54.405 12.32,54.405 v1(12.525,54.2)
USB1_P: CN8.92 U4.AA15 | length 16.5
  Top Layer w0.1: v1(12.525,54.8) 12.525,54.725 12.65,54.6 13,54.6 17.9,59.5 23.672,59.5 24.061,59.89 24.318,59.89 24.628,59.58 U4.AA15@24.99,59.58
  Bottom Layer w0.1: CN8.92@11.1,54.75 11.7,54.75 11.855,54.595 12.32,54.595 v1(12.525,54.8)
USB2_N: CN8.86 U4.AA14 | length 16.2
  Top Layer w0.1: v1(12.525,56.3) 12.725,56.1 13.131,56.1 17.601,60.57 23.941,60.57 24.061,60.69 24.318,60.69 24.628,60.38 U4.AA14@24.99,60.38
  Bottom Layer w0.1: CN8.86@11.1,56.25 11.7,56.25 11.855,56.095 12.32,56.095 v1(12.525,56.3)
USB2_P: CN8.88 U4.AB14 | length 15.2
  Top Layer w0.1: v1(12.525,55.7) 12.735,55.91 13.21,55.91 17.68,60.38 U4.AB14@24.19,60.38
  Bottom Layer w0.1: CN8.88@11.1,55.75 11.725,55.75 11.88,55.905 12.32,55.905 v1(12.525,55.7)
USB_RENUMN: R67.2 U10.38 | length 15.8
  Top Layer w0.2: v2(81.575,88.8) v2(81.575,87.175) 81.575,87.15 v2@81.6,87.125
  Bottom Layer w0.2: U10.38@71.225,90.7 75.85,90.7 76.75,89.8 76.75,87.825 77.4,87.175 v2(81.575,87.175) 81.575,87.2 v2@81.55,87.225
  Bottom Layer w0.5: v2(81.575,88.8) R67.2@81.575,89.875
USD_DETECT: CN9.10 M1.9 U4.Y4 | length 111.1
  Top Layer w0.1: U4.Y4@25.79,68.38 v1@26.18,67.99 ; v1(52.375,2.875) 53.6,1.65 61.175,1.65 ; M1.9@61.775,4.475 61.775,2.95 61.175,2.35 61.175,1.65 ; v1(78.625,2.775) 68.6,2.775 67.125,1.3 61.525,1.3 61.175,1.65
  Signal Layer 3 w0.1: v1(26.18,67.985) 26.18,67.48 26.84,66.82 29.755,66.82 31.445,65.13 31.935,65.13 32.14,64.925 32.14,64.435 32.975,63.6 32.975,55.6 34.675,53.9 34.675,47.025 52.375,29.325 v1(52.375,2.875)
  Bottom Layer w0.1: v1(78.625,2.775) CN9.10@80.6,2.775
USD_LDO_SEL: M1.1 R41.2 U4.V7 | length 75.6
  Top Layer w0.1: v1@27,66.37 U4.V7@27.39,65.98 ; v1(51.925,12.2) 57.8,12.2 58.25,11.75 R41.2@58.25,11.125 M1.1@59.625,11.125
  Signal Layer 3 w0.1: v1(27,66.375) 27.4,65.975 29.925,65.975 30.625,65.275 30.625,64.6 30.975,64.25 31.6,64.25 32.2,63.65 32.2,55.005 32.475,54.73 32.735,54.73 32.94,54.525 32.94,54.285 33.3,53.925 33.3,47.95 51.925,29.325 v1(51.925,12.2)
uSD_LS_EN: R45.1 U4.D5 | length 77.5
  Top Layer w0.1: U4.D5@38.59,67.58 v1@38.98,67.97 ; v1(54.5,6.1) R45.1@55.25,6.1
  Signal Layer 2 w0.1: v1(38.985,67.97) 39.104,67.85 39.93,67.85 40.78,67 v1(53.4,67)
  Bottom Layer w0.1: v1(53.4,67) 53.4,42.2 54.5,41.1 v1(54.5,6.1)
VBUS_OTG: CN8.11 CN8.13 CN8.15 R85.2 | length 47.3
  Signal Layer 2 w0.5: v2(3.275,79.75) v2(3.275,78.975) 3.7,78.55 11.531,78.55 12.481,79.5 13.375,79.5 13.4,79.475 15.303,79.475 16.453,80.625 29.875,80.625 30.8,81.55 36.8,81.55 v2(38.175,82.925) 38.725,83.475 v2(38.75,83.475)
  Bottom Layer w0.3: v2@3.175,79.75 v2(3.275,79.75) ; 3.275,79.3 v2(3.275,79.75) ; 3.275,79.3 v2(3.275,78.975) 3.5,78.75 CN8.15@4.9,78.75 CN8.13@4.9,79.25 ; 3.275,79.3 3.325,79.25 CN8.13@4.9,79.25 ; v2(3.275,79.75) CN8.11@4.9,79.75 CN8.13@4.9,79.25
  Bottom Layer w0.5: v2(38.175,82.925) 38.2,82.925 v2(38.75,83.475) 38.75,83.798 R85.2@39.302,84.35
VBUS_SW: CN8.19 CN8.21 CN8.23 R84.2 | length 61.7
  Signal Layer 2 w0.7: v2(3.375,76.75) 3.125,76.75 v2(2.675,77.2) ; v2(41.35,83.525) 40.6,83.525 39.85,83.525 v2(39.825,83.55) v2(40.6,83.55) 40.213,83.938 39.425,84.725 36.65,84.725 35.45,83.525 29.85,83.525 28.69,82.365 13.14,82.365 11.425,80.65 2,80.65 1.55,80.2 1.55,77.875 2.225,77.2 v2(2.675,77.2) ; v2(2.675,77.2) v2@2.686,77.2 ; v2@2.686,77.2 2.975,77.2 3.375,76.8 v2(3.375,77.65) 3.136,77.65 v2@2.686,77.2
  Bottom Layer w0.3: v2(3.375,76.75) 3.125,76.75 v2(2.675,77.2) 3.125,77.65 v2(3.375,77.65) ; v2(3.375,76.75) 3.375,77.25 ; v2(3.375,76.75) CN8.23@4.9,76.75 CN8.21@4.9,77.25 ; 3.375,77.25 CN8.21@4.9,77.25 ; 3.375,77.25 v2(3.375,77.65) ; v2(3.375,77.65) 3.375,77.75 CN8.19@4.9,77.75 CN8.21@4.9,77.25
  Bottom Layer w0.5: R84.2@40.827,84.102 R84.2@40.827,84.35
  Bottom Layer w0.7: v2(39.825,83.55) v2(40.6,83.55) ; 40.827,83.777 v2(40.6,83.55) ; v2(41.35,83.525) 41.325,83.55 v2(40.6,83.55)
  Bottom Layer w0.9: 40.827,83.777 R84.2@40.827,84.102
VDD: C79.2 C80.2 C82.2 C84.2 C87.2 C91.2 C92.2 C94.2 C95.1 C111.2 CN7.8 CN7.10 JP3.1 M1.22 M1.25 R8.2 R11.1 R12.1 R13.1 R15.2 R30.2 R31.2 R33.2 R34.2 R35.2 R38.2 R39.2 R43.2 R49.2 R53.1 R64.1 R82.2 R93.1 R95.1 R99.2 R100.2 R101.1 R300.1 R900.2 R901.2 SB1.2 SB4.2 U3.31 U4.A14 U4.D18 U4.M6 U4.M9 U4.N5 U4.N8 U4.N10 U4.P9 U4.P11 U4.R10 U4.R12 U4.T13 U4.U9 U4.U12 U4.U14 U5.C6 U5.M4 U5.N4 U5.P3 U5.P5 | length 242.9
  Top Layer w0.1: v1(47.875,100.125) 47.875,98.74 U3.31@47.879,98.736
  Top Layer w0.2: U4.U14@28.19,60.38 U4.U14@28.218,60.408 ; U4.U14@28.25,60.375 U4.U14@28.218,60.408 ; v2(28.425,97.5) v2@28.45,97.475 ; v1(28.59,62.38) U4.U12@28.19,61.98 28.19,61.915 27.8,61.525 27.8,60.825 U4.U14@28.217,60.408 ; v1@28.6,62.4 28.6,63.05 28.775,63.225 28.775,63.795 U4.U9@28.19,64.38 v1(28.59,64.78) v1(29.34,65.53) ; v1(30.19,61.58) U4.R12@29.79,61.98 ; v1(30.19,64.78) U4.P9@30.59,64.38 ; U4.N10@31.39,63.58 U4.P9@30.59,64.38 ; U4.N8@31.39,65.18 v1(31.79,64.78) U4.M9@32.19,64.38 ; U4.N5@31.39,67.58 v1(31.79,67.18) U4.M6@32.19,66.78 ; U4.D18@38.59,57.18 38.97,56.8 41.5,56.8 v2(41.8,56.5) ; U5.C6@56.775,61.65 56.8,61.65 v1(57.3,62.15) ; U5.M4@61.275,60.65 U5.N4@61.775,60.65 ; U5.P5@62.275,61.15 U5.N4@61.775,60.65 ; v1(63.425,60.15) U5.P3@62.275,60.15 U5.N4@61.775,60.65 ; U4.U14@28.218,60.408 U4.T13@28.99,61.18 U4.R12@29.79,61.98 ; U4.R12@29.79,61.98 U4.P11@30.59,62.78 v1(30.19,63.18) U4.R10@29.79,63.58 U4.P9@30.59,64.38
  Top Layer w0.3: R8.2@8.4,110.2 v2(9.2,110.2) ; R11.1@12.3,104.6 v2(12.3,105.3) ; R12.1@13.575,104.6 v2(13.575,105.3) ; R13.1@14.825,104.6 v2(14.825,105.3) ; v2(15.775,53.525) R34.2@15.775,54.35 R35.2@16.85,54.35 ; v2(17.2,93.525) SB4.2@17.2,94.7 ; v2(22.1,93.554) SB1.2@22.1,94.729 ; v2(31.675,79.925) v2(32.675,79.925) 33.825,79.925 v2(33.95,79.8) ; U4.A14@40.99,60.38 42.13,60.38 42.25,60.5 v2(42.25,60.575) ; R31.2@46,72.325 v2(46.75,72.325) ; R30.2@46,73.4 v2(46.75,73.4) ; v2(56.625,8.075) R43.2@57.35,8.075 ; M1.25@61.775,11.775 v2(61.775,12.5) ; R33.2@61.925,55.7 v2(62.725,55.7) ; R38.2@62.775,14.15 v2(62.775,14.875) ; R39.2@63.775,14.15 v2(63.775,14.875) ; R49.2@63.925,2 63.975,2.05 v2(64.825,2.05) ; M1.22@64.775,11.775 v2(64.775,12.5)
  Top Layer w0.4: v2(17.35,77.8) R300.1@17.85,78.3 ; v2@28.45,97.475 R15.2@29.5,97.475
  Signal Layer 2 w0.1: v1@41.65,94.75 41.687,94.788 41.687,94.8 v1@41.687,94.813 ; v1(41.675,94.8) v1@41.687,94.813 ; v1(47.875,100.125) 47.875,99.605 43.945,95.675 42.55,95.675 ; v1@41.687,94.813 42.55,95.675 ; v1@41.687,94.813 42.55,95.675
  Signal Layer 2 w0.2: v1@30.175,61.575 30.185,61.585 30.19,61.59 v1(30.19,63.18) v1(30.19,64.78) ; v1(30.19,61.58) 31.12,60.65 34.25,60.65 34.725,60.175 36.85,60.175 37.3,60.625 42.25,60.625 v2@42.375,60.625
  Signal Layer 3 w0.3: v2(9.2,110.2) 9.2,108.4 v2(12.3,105.3) ; v2(31.675,79.925) v2(32.675,79.925) 33.825,79.925 v2(33.95,79.8)
  Signal Layer 4 w0.1: v1(41.675,94.8) 41.375,94.5 41.375,91.95 43.025,90.3 43.025,85.3 42.725,85 42.05,85 42,85
  Signal Layer 4 w0.2: 25.96,62.79 28.435,62.79 28.525,62.7 ; 25.961,64.387 28.313,64.387 28.425,64.275 ; v1(31.79,64.78) 31.39,65.18 31.39,66.78 v1(31.79,67.18)
  Signal Layer 4 w0.3: v2(15.775,53.525) 15.775,60.247 19.915,64.387 25.325,64.387 ; JP3.1@23.8,99.935 JP3.1@23.805,99.93 ; 25.96,62.79 25.325,63.425 25.325,64.387 ; 25.961,64.387 25.325,64.387 ; v2(28.425,97.5) 28.425,84.85 32.475,80.8 32.475,79.925 v2@32.475,79.8 ; v1(29.34,65.53) 28.7,66.17 28.7,67.275 30,68.575 31.175,68.575 ; v1(30.19,63.18) 30.72,62.65 ; v1(31.79,67.18) 31.175,67.794 31.175,68.575 ; v2(40.888,94.537) 40.888,91.763 42.55,90.1 ; 42.575,90.075 42.575,85.525 42.05,85 42.025,84.975 39.425,84.975 34.25,79.8 v2(33.95,79.8) 32.675,79.8 v2@32.475,79.8 ; 31.175,68.575 31.975,69.375 31.975,79.3 v2@32.475,79.8
  Bottom Layer w0.1: v2@40.875,94.525 v2(40.888,94.537)
  Bottom Layer w0.12: C79.2@31.69,65.58 C79.2@31.79,65.48
  Bottom Layer w0.2: R99.2@25.9,62.525 27.364,62.525 27.629,62.79 27.96,62.79 28.37,62.38 v1(28.59,62.38) ; C82.2@27.915,64.78 v1(28.59,64.78) ; C87.2@28.49,63.18 28.59,63.08 v1(28.59,62.38) ; v1(29.34,65.53) 29.39,65.58 C80.2@29.99,65.58 29.99,64.98 v1(30.19,64.78) 29.99,64.58 C84.2@29.99,64.08 ; C84.2@29.99,63.98 29.965,64.005 29.965,63.405 v1(30.19,63.18) 29.99,62.98 C91.2@29.99,62.28 29.99,61.78 v1(30.19,61.58) 29.265,61.58 C94.2@29.19,61.655 29.19,61.78 v1(28.59,62.38) ; v1(31.79,64.78) C79.2@31.79,65.48 ; R64.1@39.75,94.525 v2@40.875,94.525 ; R100.2@60.775,60.6 61.2,60.175 C95.1@61.975,60.175
  Bottom Layer w0.3: R93.1@40,79.475 v2(40,82.35) ; C111.2@40.95,56.8 41.5,56.8 v2(41.8,56.5) 41.8,60.125 v2(42.25,60.575) 42.6,60.225 R101.1@43.675,60.225 ; R53.1@41.075,79.475 41.075,82.35 v2(41.1,82.375) ; R900.2@56.05,60.9 56.45,61.3 C92.2@56.45,62.15 ; v1(57.3,62.15) 57.55,62.4 R901.2@57.55,63.4 ; C95.1@61.975,60.175 63.4,60.175 v1(63.425,60.15) v1@63.45,60.125 ; v2(79.325,81.375) 79.325,80.75 ; 79.325,80.75 79.325,80.55 79.625,80.25 CN7.10@81.1,80.25 82.35,80.25 82.5,80.4 v2(82.5,80.75) CN7.8@81.1,80.75 79.325,80.75 ; 31.675,79.125 32.2,78.6 R95.1@34.3,78.6 34.3,79.45 v2(33.95,79.8) 33.825,79.925 v2(32.675,79.925) v2(31.675,79.925) 31.675,79.125
  Bottom Layer w0.4: C92.2@56.45,62.15 v1(57.3,62.15)
  Bottom Layer w0.6: v2@43.6,82.65 43.825,82.875 v2(43.825,83.325) ; R82.2@44.202,84.35 44.202,83.702 ; v2(46.75,72.325) v2(46.75,73.4) 46.75,80.525 v2(44.475,82.8) ; v2(43.825,83.325) 44.35,82.8 v2(44.475,82.8) ; v2(43.825,83.325) 44.202,83.702 ; 44.202,83.702 44.202,83.325 44.202,83.073 v2(44.475,82.8)
  other v2: 43.6,82.625
VDD_CORE: C77.2 C78.2 C83.2 C85.2 C86.2 C88.2 C89.2 C90.2 C96.2 C98.2 C99.2 C100.2 C101.2 C103.2 C104.2 LNK1.2 R81.2 U4.H9 U4.H11 U4.H13 U4.H15 U4.J8 U4.J10 U4.J12 U4.J14 U4.K9 U4.K11 U4.K13 U4.K15 U4.L8 U4.L10 U4.L12 U4.L14 U4.M11 U4.M13 U4.M15 U4.N12 U4.N14 U4.P13 U4.P15 U4.R14 U4.T15 | length 51.2
  Top Layer w0.12: U4.N12@31.39,61.98 v1(31.79,61.58) 32.19,61.18 32.99,60.38 v1(33.39,59.98) ; U4.K15@33.76,59.61 U4.K15@33.78,59.61
  Top Layer w0.2: v1(28.59,59.98) U4.T15@28.99,59.58 v1(29.39,59.98) U4.R14@29.79,60.38 ; U4.P15@30.56,59.59 30.56,59.61 v1(30.19,59.98) U4.R14@29.79,60.38 ; v1(31.79,63.18) 32.16,62.81 32.18,62.81 32.2,62.79 33,61.99 33.01,61.98 33.01,61.96 v1(33.39,61.58) U4.K13@33.79,61.18 U4.J14@34.59,60.38 34.89,60.68 v1(35.09,60.68) ; U4.M15@32.18,59.61 32.16,59.61 v1(31.775,59.995) 31.39,60.38 U4.P13@30.59,61.18 U4.R14@29.79,60.38 ; U4.M15@32.19,59.58 32.245,59.58 32.425,59.4 33.625,59.4 U4.K15@33.75,59.525 ; U4.L10@32.99,63.58 v1(33.39,63.18) U4.K11@33.79,62.78 U4.J12@34.59,61.98 34.715,61.98 34.79,62.055 35.065,62.055 v1(35.09,62.08) ; U4.L8@32.99,65.18 v1(33.39,64.78) U4.K9@33.79,64.38 U4.J10@34.59,63.58 34.715,63.58 34.815,63.48 v1(35.09,63.48) ; v1(33.39,59.98) U4.K15@33.76,59.61 ; U4.K15@33.79,59.58 33.995,59.375 35.2,59.375 U4.H15@35.375,59.55 ; U4.J8@34.59,65.18 34.79,65.18 v1(35.09,64.88) 35.39,64.58 U4.H9@35.39,64.38 35.39,63.78 v1(35.09,63.48) ; U4.H15@35.38,59.64 35.09,59.93 v1(35.09,60.68) ; v1(35.09,60.68) 35.39,60.98 U4.H13@35.39,61.18 35.39,61.78 v1(35.09,62.08) ; v1(35.09,62.08) 35.39,62.38 U4.H11@35.39,62.78 35.39,63.18 v1(35.09,63.48)
  Signal Layer 4 w0.2: 41.05,61.275 41.05,60.325 LNK1.2@41.6,59.775
  Signal Layer 4 w0.5: v1(35.09,64.88) 35.09,65.315 35.35,65.575
  Bottom Layer w0.2: v1(28.59,59.98) 28.59,60.08 C101.2@29.19,60.68 29.39,60.48 v1(29.39,59.98) ; C100.2@29.99,60.68 30.19,60.48 v1(30.19,59.98) ; C86.2@31.69,63.98 31.79,63.88 v1(31.79,63.18) 31.69,63.08 C90.2@31.69,62.38 31.79,62.28 v1(31.79,61.58) 31.69,61.48 C99.2@31.69,60.78 31.775,60.695 v1(31.775,59.995) ; C104.2@33.39,59.155 v1(33.39,59.98) C98.2@33.39,60.78 v1(33.39,61.58) C89.2@33.39,62.38 v1(33.39,63.18) C85.2@33.39,63.98 v1(33.39,64.78) C78.2@33.39,65.58 ; C103.2@35.09,59.98 v1(35.09,60.68) C96.2@35.09,61.38 v1(35.09,62.08) C88.2@35.09,62.78 v1(35.09,63.48) C83.2@35.09,64.18 v1(35.09,64.88) C77.2@35.09,65.58
  other v2: 45.65,83.225 46.45,83.225 47.325,83.475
